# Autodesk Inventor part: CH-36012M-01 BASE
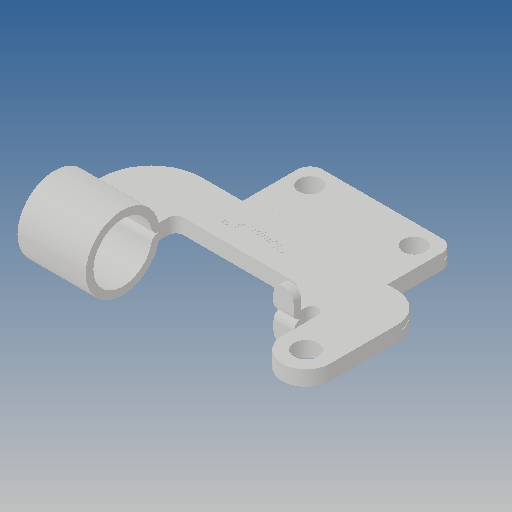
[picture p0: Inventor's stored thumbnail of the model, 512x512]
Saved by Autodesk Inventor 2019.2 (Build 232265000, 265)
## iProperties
Created: 2012-09
Part Number: CH-36012M-01 BASE
Material: Ogólny
Document SubType Name: Modeling
Designer: CADENGINEERING4
Density: 1 g/cm^3
Appearance: Domyślna
Author: CADENGINEERING4
Revision Number: ÈÎºÎ
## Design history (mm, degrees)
feature "À­Éì8[1]"
feature "À­Éì8[2]"
feature "À­Éì12[1]"
feature "À­Éì12[2]"
node "Bryła1"
node "Bryła2"
node "Bryła3"
node "Bryła4"
